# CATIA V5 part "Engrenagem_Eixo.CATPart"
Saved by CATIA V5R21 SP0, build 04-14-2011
Part number: Engrenagem_Eixo
Bounding box of the stored display mesh (mm): x 0 to 19, y -12.98 to 12.993, z -12.835 to 13
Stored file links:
  D:\CATIA\CADs\CHASSI\Direita\Motor\Engrenagem_Eixo.CATPart
  D:\CATIA\CADs\CHASSI\Direita\Motor\Engrenagem.CATPart
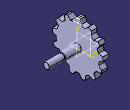
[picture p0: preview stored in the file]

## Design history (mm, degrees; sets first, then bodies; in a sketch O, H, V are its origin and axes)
Body1 (main body)
Body2
  Sketch1 on yz-plane, origin (0, 0, 0), H (0, 1, 0), V (0, 0, 1)
    circle A1 centre (0, 0) radius 11
    circle A2 centre (0, 0) radius 1.5
    point P1 (0, 1.5)
    radius A1 = 11
    radius A2 = 1.5
    coincidence: A2 P1, P1 V
  Pad1: profile Sketch1, direction (1, 0, 0), length 3
  Sketch2 on end face of Pad1, origin (3, 0, 0), H (0, 1, 0), V (0, 0, 1)
    arc A1 centre (0, 0) radius 11 from (1.6165, 10.8806) to (0, 11) ccw
    arc A2 centre (0, 0) radius 13 from (0.92, 12.9674) to (0, 13) ccw
    point P1 (0, 13)
    point P2 (1.6165, 10.8806)
    line L1 (0.92, 12.9674) -> (1.6165, 10.8806)
    point P3 (0.92, 12.9674)
    point P4 (1.6012, 10.9265)
    point P5 (0, 11)
    axis line L2 (0, 13) -> (0, 0)
    point P6 (0, 13)
    point P7 (-0.92, 12.9674)
    arc A3 centre (0, 0) radius 13 from (-0.92, 12.9674) to (0, 13) cw
    point P9 (-1.6165, 10.8806)
    line L3 (-0.92, 12.9674) -> (-1.6165, 10.8806)
    point P10 (0, 11)
    arc A4 centre (0, 0) radius 11 from (-1.6165, 10.8806) to (0, 11) cw
    radius A1 = 11
    radius A2 = 13
    length L1 = 2.2
    distance P7 P3 = 1.84
    coincidence: P1 V, P4 L1
    vertical: L2 V
    symmetry: P1 P6 L2, P3 P7 L2, A2 A3 L2, P2 P9 L2, L1 L3 L2, P5 P10 L2, A1 A4 L2
  Pad2: profile Sketch2, direction (1, 0, 0), length -3
  CircPattern1: of the body so far, instances 13, angular step 27.6, axis from face of Pad1 from Sketch1.A1
  Sketch3 on face of CircPattern1, origin (3, 0, 0), H (0, 1, 0), V (0, 0, 1)
    circle A1 centre (0, 0) radius 2
    radius A1 = 2
  Pad3: profile Sketch3, direction (1, 0, 0), length 8
  Sketch4 on end face of Pad3, origin (11, 0, 0), H (0, 1, 0), V (0, 0, 1)
    circle A1 centre (0, 0) radius 1.5
    radius A1 = 1.5
  Pad4: profile Sketch4, direction (1, 0, 0), length 8
  Sketch5 on start face of Pad3, origin (3, 0, 0), H (0, -1, 0), V (0, 0, 1)
    circle A1 centre (0, 0) radius 1.5
  Pocket1: profile Sketch5, direction (1, 0, 0), length 6
  Sketch6 on end face of Pad1, origin (3, 0, 0), H (0, 1, 0), V (0, 0, 1)
    circle A1 centre (0, 0) radius 11
    circle A2 centre (0, 0) radius 1.5
    point P1 (0, 1.5)
    radius A1 = 11
    radius A2 = 1.5
    coincidence: A2 P1, P1 V
  Pad5: profile Sketch6, direction (1, 0, 0), length 3
Current feature: Pocket1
